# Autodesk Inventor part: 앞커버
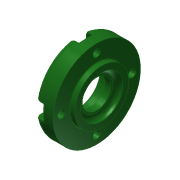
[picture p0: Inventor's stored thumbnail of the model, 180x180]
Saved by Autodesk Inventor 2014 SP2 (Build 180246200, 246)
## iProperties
Created: 2015-11
Part Number: 앞커버
Material: 알루미늄 6061
Document SubType Name: Modeling
Designer: mduedu
Density: 1 g/cm^3
Appearance: 매끄러움 - 짙은 산림 녹색
Author: mduedu
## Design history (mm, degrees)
sketch "스케치1"
  geometry: L1 (-7, 0)-(7, 0); L2 (-7, 0)-(-7, 26); L3 (-7, 26)-(4, 26); L4 (4, 26)-(4, 16); L5 (4, 16)-(7, 16); L6 (7, 16)-(7, 0); 2 further points
  constraints: 12 end point, 3 perpendicular, 2 parallel, 1 coincident, 1 horizontal, 1 midpoint
  dimensions: "d0" = 14 distance of L1.start L1.end; "d1" = 52 diameter of L3 L1; "d2" = 3 distance of L4.end L5.end; "d3" = 32 diameter of L5 L1
revolve "회전1" sketch "스케치1" stored, may be unused: angle "d4" = 90 deg
hole "구멍1" diameter "d7" = 25; stored, may be unused: countersink angle "d11" = 90 deg, drill point angle "d13" = 0 deg; dims "d5" = 10, "d6" = 10, "d8" = 6, "d9" = 4, "d10" = 2, "d12" = 3
hole "구멍2" diameter "d16" = 25; stored, may be unused: countersink angle "d20" = 90 deg, drill point angle "d22" = 0 deg; dims "d17" = 6, "d18" = 4, "d19" = 2, "d21" = 7.3, "d62" = 10, "d63" = 10
hole "구멍3" diameter "d25" = 17; stored, may be unused: countersink angle "d29" = 90 deg, drill point angle "d31" = 0 deg; dims "d23" = 10, "d24" = 10, "d26" = 6, "d27" = 4, "d28" = 2, "d30" = 4.2
chamfer "모따기1" distance "d32" = 0.7; stored, may be unused: second distance "d33" = 2, angle "d34" = 30 deg
fillet "모깎기1" dims "d35" = 0.3
fillet "모깎기2" dims "d36" = 3
fillet "모깎기3" dims "d37" = 3
fillet "모깎기4" dims "d38" = 0.3
sketch "스케치3" dims "d61" = 42
  geometry: C1 r 26 at (0, 0) reference; 2 further points
  constraints: 2 vertical alignment, 1 coincident, 2 other
hole "구멍4" sketch "스케치3" at (0, -21) diameter "d44" = 4.5; stored, may be unused: countersink angle "d48" = 90 deg, drill point angle "d50" = 0 deg; dims "d45" = 6, "d46" = 8, "d47" = 4.6, "d49" = 8
sketch "스케치4"
  geometry: L1 (-4, 0)-(-4, -4.69); L2 (4, 0)-(4, -4.69); A1 r 4 centre (0, 0) between (3.614, -1.714) and (-3.614, -1.714) reference; A2 r 26 centre (0, 21) between (-4, -4.69) and (4, -4.69) reference; 1 further point
  constraints: 4 end point, 4 point on circle, 2 tangent, 1 parallel, 1 vertical
extrude "돌출1" cut sketch "스케치4" stored distance "d51" = 0; taper "d52" = 0 deg
fillet "모깎기5" dims "d56" = 0.3
fillet "모깎기6" dims "d57" = 1
node "솔리드1"
pattern_circular "원형 패턴1" dims angle "d54" = 360 deg
